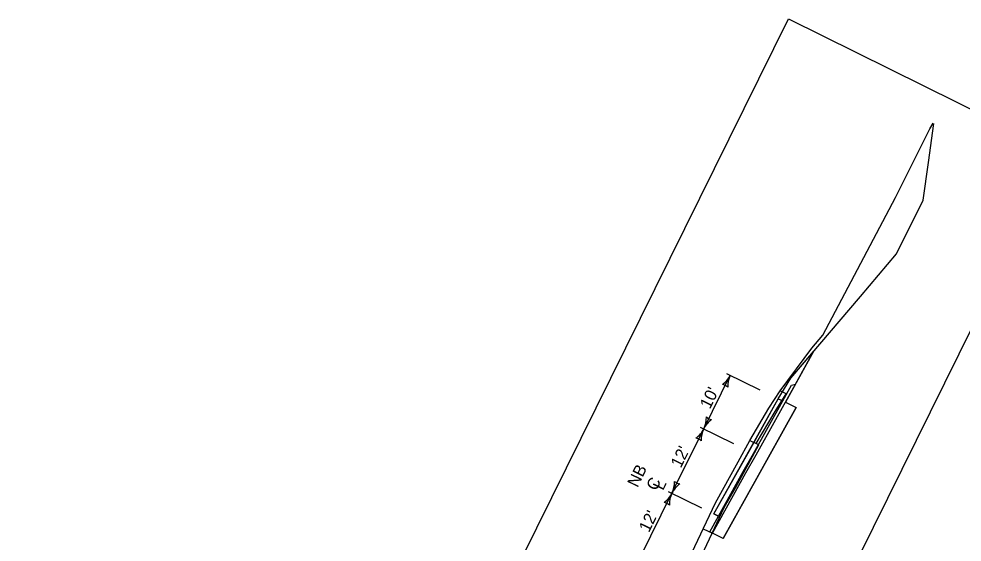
# Model space of a CAD drawing. Extents: x 14104283 to 14121738, y 8635219 to 8671666.
# Drawn here: x 14117425 to 14118056, y 8668888 to 8669238 of the extents above; entities that cross this region are included whole.
import ezdxf

# ---------------------------------------------------------------- set-up
doc = ezdxf.new("R2010")
doc.units = 0
for name, color, linetype in [('Default', 7, 'Continuous'), ('dsnCellElements', 7, 'Continuous'), ('dsnShadingPaved', 7, 'Continuous'), ('dsnTextFinalPlan', 7, 'Continuous'), ('TC_Subbase', 7, 'Continuous'), ('TC_SubgradeTreatment', 7, 'Continuous'), ('TC_SubstrataExistingPavement', 7, 'Continuous'), ('Terrain', 7, 'Continuous')]:
    doc.layers.add(name, color=color, linetype=linetype)

# ---------------------------------------------------------------- blocks, each defined once
blk = doc.blocks.new('LT')
at = {"layer": 'dsnCellElements'}
for centre, radius, start, end in [((-3.56, 0), 1.64, 342.2666, 17.7333), ((0, 4.25), 4.25, 241.9275, 270), ((0, -4.25), 4.25, 90, 118.0725)]:
    blk.add_arc(centre, radius, start, end, dxfattribs=at)

msp = doc.modelspace()

# ---------------------------------------------------------------- linework, layer by layer
at = {"layer": 'Default'}
for p, q in [((14117933.08, 8668984.23), (14117936.07, 8668982.75)), ((14117890.1, 8668907.19), (14117893.09, 8668905.71))]:
    msp.add_line(p, q, dxfattribs=at)
for points in [[(14117890.1, 8668907.19), (14117906.75, 8668937.03), (14117913.54, 8668949.21), (14117933.08, 8668984.23)], [(14117893.09, 8668905.71), (14117909.74, 8668935.55), (14117916.53, 8668947.73), (14117936.07, 8668982.75)]]:
    msp.add_lwpolyline(points, dxfattribs=at)
at = {"layer": 'dsnShadingPaved'}
msp.add_lwpolyline([(14117890.1, 8668907.19), (14117933.08, 8668984.23), (14117941.61, 8668997.88), (14117956.75, 8669015.72), (14117937.86, 8668981.86), (14117945.02, 8668978.28), (14117896.19, 8668890.75), (14117887.24, 8668895.21), (14117893.09, 8668905.71)], close=True, dxfattribs=at)
at = {"layer": 'dsnTextFinalPlan'}
for p, q in [((14117883.31, 8668964.1), (14117901.03, 8668999.95)), ((14117898.58, 8669001.17), (14117920.81, 8668990.18)), ((14117862.03, 8668921.07), (14117883.31, 8668964.1)), ((14117880.85, 8668965.31), (14117903.08, 8668954.32)), ((14117840.76, 8668878.04), (14117862.03, 8668921.07)), ((14117859.58, 8668922.28), (14117881.81, 8668911.29))]:
    msp.add_line(p, q, dxfattribs=at)
msp.add_lwpolyline([(14117425.32, 8668197.46), (14117939.89, 8669238.2), (14118120.52, 8669148.89), (14117605.96, 8668108.15)], close=True, dxfattribs=at)
at = {"layer": 'TC_Subbase'}
for p, q in [((14117944.65, 8668994.03), (14117956.75, 8669015.72)), ((14117936.07, 8668982.75), (14117941.93, 8668993.25)), ((14117941.93, 8668993.25), (14117944.65, 8668994.03)), ((14117887.24, 8668895.21), (14117893.09, 8668905.71)), ((14117882.97, 8668897.33), (14117889.03, 8668894.33))]:
    msp.add_line(p, q, dxfattribs=at)
msp.add_lwpolyline([(14117889.03, 8668894.33), (14117911.53, 8668934.66), (14117918.32, 8668946.84), (14117944.65, 8668994.03)], dxfattribs=at)
at = {"layer": 'TC_SubgradeTreatment'}
for p, q in [((14117937.86, 8668981.86), (14117945.02, 8668978.28)), ((14117896.19, 8668890.75), (14117889.03, 8668894.33))]:
    msp.add_line(p, q, dxfattribs=at)
msp.add_lwpolyline([(14117896.19, 8668890.75), (14117918.68, 8668931.08), (14117925.48, 8668943.26), (14117945.02, 8668978.28)], dxfattribs=at)
at = {"layer": 'TC_SubstrataExistingPavement'}
for points in [[(14117914.07, 8668956.41), (14117918.25, 8668954.35), (14117930.94, 8668975.78), (14117938.49, 8668987.41), (14117934.3, 8668989.47)], [(14117872.76, 8668875.6), (14117878.74, 8668872.65), (14117883.84, 8668883.51), (14117897.03, 8668911.61), (14117904.48, 8668924.61), (14117920.04, 8668953.46), (14117918.25, 8668954.35)]]:
    msp.add_lwpolyline(points, dxfattribs=at)
at = {"layer": 'Terrain'}
for points in [[(14117933.08, 8668984.23), (14117941.61, 8668997.88), (14117988.08, 8669052.64), (14118012.27, 8669081.14), (14118030.04, 8669117.09), (14118033.53, 8669142.17), (14118037.15, 8669168.17)], [(14118011.55, 8669118.68), (14118013.7, 8669123.32), (14118034.37, 8669164.77), (14118036.69, 8669168.4)], [(14117867.27, 8668864.86), (14117870.35, 8668870.45), (14117873.37, 8668876.88), (14117891.05, 8668914.56), (14117906.28, 8668941.99), (14117914.07, 8668956.41), (14117926.76, 8668977.85), (14117934.3, 8668989.47), (14117955.56, 8669017.99), (14117963.01, 8669026.83), (14118011.55, 8669118.68)]]:
    msp.add_lwpolyline(points, dxfattribs=at)

# ---------------------------------------------------------------- block references
at = {"layer": 'dsnTextFinalPlan'}
for p, xscale, yscale, rotation in [((14117901.03, 8668999.95), 3.942400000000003, 3.9424000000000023, 63.69110745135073), ((14117883.31, 8668964.1), 3.942400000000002, 3.9424000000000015, -116.30889254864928), ((14117883.31, 8668964.1), 3.942400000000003, 3.9424000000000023, 63.69110745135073), ((14117862.03, 8668921.07), 3.942400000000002, 3.9424000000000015, -116.30889254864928), ((14117862.03, 8668921.07), 3.942400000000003, 3.9424000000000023, 63.69110745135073)]:
    msp.add_blockref('LT', p, dxfattribs=dict(at, xscale=xscale, yscale=yscale, rotation=rotation))

# ---------------------------------------------------------------- texts
for s, p in [("10'", (14117887.41, 8668976.88)), ("12'", (14117867.91, 8668937.44)), ('NB', (14117838.97, 8668924.39)), ('C', (14117851.59, 8668922.19)), ('L', (14117856.04, 8668922.44)), ("12'", (14117846.64, 8668894.41))]:
    msp.add_text(s, height=8, rotation=63.69111, dxfattribs=at).set_placement(p)

doc.saveas('drawing.dxf')
